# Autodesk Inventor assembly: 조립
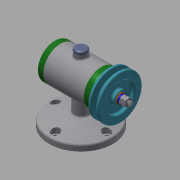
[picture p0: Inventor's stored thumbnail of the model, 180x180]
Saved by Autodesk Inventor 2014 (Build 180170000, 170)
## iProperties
Created: 2018-12
Part Number: 조립
Document SubType Name: Assembly
Designer: kh
Author: kh
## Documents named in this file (15)
- C:\Users\kh\Desktop\481207V1012\조립.iam
- C:\Users\kh\Desktop\481207V1012\본체.ipt
- C:\Users\kh\Desktop\481207V1012\V벨트풀리.ipt
- C:\Users\kh\Desktop\481207V1012\고무캡.ipt
- C:\Users\kh\Desktop\481207V1012\너트 M8.ipt
- 너트 M8.ipt
- C:\Users\kh\Desktop\481207V1012\뒤커버.ipt
- C:\Users\kh\Desktop\481207V1012\베어링 15 x 32 x 9.ipt
- C:\Users\kh\Desktop\481207V1012\볼트 M4 x 12.ipt
- C:\Users\kh\Desktop\481207V1012\스프링와셔 8.ipt
- C:\Users\kh\Desktop\481207V1012\앞커버.ipt
- C:\Users\kh\Desktop\481207V1012\오일 실 15 25 7.ipt
- C:\Users\kh\Desktop\481207V1012\와셔 8x17.ipt
- C:\Users\kh\Desktop\481207V1012\축.ipt
- C:\Users\kh\Desktop\481207V1012\키 3 x 3 x 12.ipt
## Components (2 placed, 2 different names)
1. V벨트풀리:1 — Insert:9, Mate:1, Insert:10
2. 고무캡:1 — Insert:15
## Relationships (4: Insert 3, Mate 1)
- Insert:9: V벨트풀리:1
- Mate:1: V벨트풀리:1
- Insert:10: V벨트풀리:1
- Insert:15: 고무캡:1
